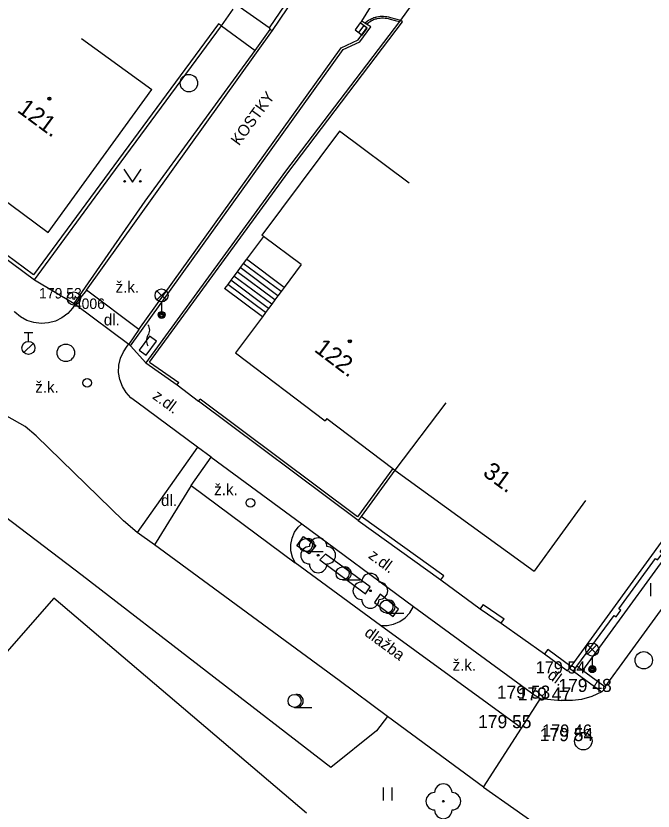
# Model space of a CAD drawing. Extents: x -538441 to -536770, y -1181008 to -1179809.
# Drawn here: x -537585.27 to -537548.66, y -1180631.14 to -1180585.46 of the extents above; entities that cross this region are included whole.
import ezdxf

# ---------------------------------------------------------------- set-up
doc = ezdxf.new("R2010")
doc.units = 0
for name, color, linetype in [('Vrstva 10', 7, 'Continuous'), ('Vrstva 11', 7, 'Continuous'), ('Vrstva 21', 7, 'Continuous'), ('Vrstva 22', 7, 'Continuous'), ('Vrstva 23', 7, 'Continuous'), ('Vrstva 24', 7, 'Continuous'), ('Vrstva 27', 7, 'Continuous'), ('Vrstva 28', 7, 'Continuous'), ('Vrstva 33', 7, 'Continuous'), ('Vrstva 36', 7, 'Continuous'), ('Vrstva 39', 7, 'Continuous'), ('Vrstva 4', 7, 'Continuous'), ('Vrstva 40', 7, 'Continuous'), ('Vrstva 47', 7, 'Continuous'), ('Vrstva 5', 7, 'Continuous'), ('Vrstva 7', 7, 'Continuous'), ('Vrstva 8', 7, 'Continuous')]:
    doc.layers.add(name, color=color, linetype=linetype)

msp = doc.modelspace()

# ---------------------------------------------------------------- linework, layer by layer
at = {"layer": 'Vrstva 10'}
for p, q in [((-537565.39, -1180585.76), (-537561.54, -1180579.49)), ((-537570.52, -1180586.29), (-537567.1, -1180581.19)), ((-537565.48, -1180585.86), (-537565.39, -1180585.76)), ((-537581.222, -1180601.219), (-537570.52, -1180586.29)), ((-537578.205, -1180603.471), (-537566.58, -1180587.29)), ((-537581.222, -1180601.219), (-537581.855, -1180602.02)), ((-537578.205, -1180603.471), (-537581.222, -1180601.219)), ((-537581.855, -1180602.02), (-537582.009, -1180602.238)), ((-537581.855, -1180602.02), (-537578.787, -1180604.314)), ((-537578.205, -1180603.471), (-537578.787, -1180604.314)), ((-537578.879, -1180604.43), (-537578.787, -1180604.314)), ((-537574.844, -1180610.221), (-537578.323, -1180607.637)), ((-537579.093, -1180614.456), (-537584.102, -1180609.571)), ((-537574.844, -1180610.221), (-537578.3, -1180615.128)), ((-537574.041, -1180610.808), (-537574.844, -1180610.221)), ((-537575.196, -1180612.441), (-537574.041, -1180610.808)), ((-537574.041, -1180610.808), (-537568.847, -1180614.632)), ((-537575.196, -1180612.441), (-537577.305, -1180615.844)), ((-537575.196, -1180612.441), (-537569.213, -1180616.879)), ((-537578.3, -1180615.128), (-537579.093, -1180614.456)), ((-537544.414, -1180614.353), (-537551.437, -1180623.991)), ((-537577.305, -1180615.844), (-537578.3, -1180615.128)), ((-537566.699, -1180623.637), (-537577.305, -1180615.844)), ((-537564.327, -1180620.468), (-537569.213, -1180616.879)), ((-537562.417, -1180619.388), (-537555.435, -1180624.491)), ((-537556.21, -1180626.37), (-537564.327, -1180620.468)), ((-537563.91, -1180625.71), (-537566.699, -1180623.637)), ((-537555.435, -1180624.491), (-537555.134, -1180624.676)), ((-537556.21, -1180626.37), (-537555.134, -1180624.676)), ((-537555.134, -1180624.676), (-537553.93, -1180624.78)), ((-537558.407, -1180629.756), (-537563.91, -1180625.71)), ((-537558.407, -1180629.756), (-537556.21, -1180626.37)), ((-537558.407, -1180629.756), (-537552.23, -1180634.08))]:
    msp.add_line(p, q, dxfattribs=at)
for points in [[(-537565.225, -1180585.865), (-537565.057, -1180585.747), (-537565, -1180585.71), (-537564.912, -1180585.658), (-537564.82, -1180585.61), (-537564.755, -1180585.58), (-537564.693, -1180585.556), (-537564.634, -1180585.537), (-537564.579, -1180585.521), (-537564.527, -1180585.508), (-537564.428, -1180585.49), (-537564.341, -1180585.48), (-537564.265, -1180585.475), (-537564.198, -1180585.475), (-537564.14, -1180585.476), (-537564.038, -1180585.484), (-537563.962, -1180585.493), (-537563.85, -1180585.514), (-537563.74, -1180585.541), (-537563.455, -1180585.62), (-537563.17, -1180585.7)], [(-537566.58, -1180587.29), (-537565.6, -1180586.83), (-537565.1, -1180586.15), (-537565.48, -1180585.86)], [(-537582.009, -1180602.238), (-537582.29, -1180602.549), (-537582.624, -1180602.8), (-537583.001, -1180602.984), (-537583.405, -1180603.093), (-537583.823, -1180603.123), (-537584.238, -1180603.073), (-537584.637, -1180602.946), (-537585.004, -1180602.745), (-537585.327, -1180602.478), (-537585.371, -1180602.432)], [(-537578.323, -1180607.637), (-537578.656, -1180607.393), (-537578.937, -1180607.089), (-537579.153, -1180606.736), (-537579.298, -1180606.349), (-537579.366, -1180605.941), (-537579.354, -1180605.528), (-537579.263, -1180605.125), (-537579.096, -1180604.747), (-537578.879, -1180604.43)], [(-537584.102, -1180609.571), (-537584.746, -1180609.048), (-537585.782, -1180608.449)], [(-537569.213, -1180616.879), (-537569.376, -1180616.548), (-537569.465, -1180616.189), (-537569.474, -1180615.82), (-537569.404, -1180615.457), (-537569.258, -1180615.118), (-537569.042, -1180614.818), (-537568.847, -1180614.632)], [(-537564.327, -1180620.468), (-537563.943, -1180620.474), (-537563.566, -1180620.401), (-537563.212, -1180620.252), (-537562.897, -1180620.033), (-537562.634, -1180619.753), (-537562.417, -1180619.388)], [(-537551.6, -1180624.29), (-537552.185, -1180624.557), (-537552.76, -1180624.72), (-537553.279, -1180624.789), (-537553.93, -1180624.78)]]:
    msp.add_lwpolyline(points, dxfattribs=at)
at = {"layer": 'Vrstva 11'}
for p, q in [((-537567.3, -1180581.08), (-537570.72, -1180586.14)), ((-537573.46, -1180586.03), (-537571.528, -1180587.436)), ((-537578.691, -1180604.418), (-537566.47, -1180587.38)), ((-537570.032, -1180601.294), (-537572.205, -1180599.676)), ((-537569.852, -1180601.053), (-537572.025, -1180599.435)), ((-537570.39, -1180601.775), (-537572.563, -1180600.157)), ((-537570.211, -1180601.534), (-537572.384, -1180599.916)), ((-537570.748, -1180602.256), (-537572.921, -1180600.638)), ((-537570.569, -1180602.016), (-537572.742, -1180600.398)), ((-537571.107, -1180602.738), (-537573.28, -1180601.12)), ((-537570.927, -1180602.497), (-537573.1, -1180600.879)), ((-537545.644, -1180613.334), (-537552.706, -1180623.054)), ((-537568.847, -1180614.632), (-537562.417, -1180619.388)), ((-537583.093, -1180618.912), (-537593.47, -1180630.74)), ((-537568.58, -1180631.25), (-537583.093, -1180618.912))]:
    msp.add_line(p, q, dxfattribs=at)
for points in [[(-537570.72, -1180586.14), (-537572.71, -1180584.74), (-537570.658, -1180581.969)], [(-537565.133, -1180585.923), (-537565.001, -1180585.83), (-537564.947, -1180585.795), (-537564.863, -1180585.745), (-537564.776, -1180585.7), (-537564.716, -1180585.672), (-537564.66, -1180585.65), (-537564.605, -1180585.633), (-537564.553, -1180585.618), (-537564.506, -1180585.606), (-537564.413, -1180585.589), (-537564.332, -1180585.58), (-537564.262, -1180585.575), (-537564.199, -1180585.575), (-537564.145, -1180585.576), (-537564.048, -1180585.584), (-537563.977, -1180585.592), (-537563.871, -1180585.612), (-537563.765, -1180585.638), (-537563.482, -1180585.716), (-537563.235, -1180585.785)], [(-537570.72, -1180586.14), (-537570.65, -1180586.23), (-537570.52, -1180586.29)], [(-537566.47, -1180587.38), (-537565.5, -1180586.94), (-537564.87, -1180586.09), (-537565.133, -1180585.923), (-537565.225, -1180585.865), (-537565.39, -1180585.76)], [(-537571.528, -1180587.436), (-537570.65, -1180586.23)], [(-537577.837, -1180596.095), (-537571.528, -1180587.436)], [(-537581.926, -1180601.978), (-537577.837, -1180596.095)], [(-537571.051, -1180598.126), (-537572.025, -1180599.435), (-537572.205, -1180599.676), (-537572.384, -1180599.916), (-537572.563, -1180600.157), (-537572.742, -1180600.398), (-537572.921, -1180600.638), (-537573.1, -1180600.879), (-537573.28, -1180601.12)], [(-537584.21, -1180600.62), (-537581.926, -1180601.978), (-537581.855, -1180602.02)], [(-537577.8, -1180605.38), (-537578.691, -1180604.418), (-537578.787, -1180604.314)]]:
    msp.add_lwpolyline(points, dxfattribs=at)
at = {"layer": 'Vrstva 21'}
for points in [[(-537563.91, -1180625.71), (-537564.55, -1180626.53), (-537567.18, -1180628.63), (-537581.47, -1180617.6), (-537593.01, -1180608.83)], [(-537568.74, -1180615.36), (-537568.03, -1180615.87), (-537568.42, -1180616.36), (-537569.12, -1180615.89), (-537568.74, -1180615.36)], [(-537567.48, -1180616.37), (-537567.8, -1180616.71), (-537565.19, -1180618.65), (-537564.91, -1180618.25), (-537567.48, -1180616.37)], [(-537564.66, -1180619.15), (-537563.59, -1180619.95), (-537563.29, -1180619.53), (-537564.33, -1180618.67), (-537564.66, -1180619.15)]]:
    msp.add_lwpolyline(points, dxfattribs=at)
for radius in [0.375, 0.05]:
    msp.add_circle((-537581.94, -1180601.69), radius, dxfattribs=at)
at = {"layer": 'Vrstva 22'}
for centre in [(-537567.9, -1180616.44), (-537564.9, -1180618.48), (-537560.71, -1180630.57)]:
    msp.add_circle(centre, 0.05, dxfattribs=at)
for centre, start, end in [((-537567.9, -1180615.94), 0, 180), ((-537568.4, -1180616.44), 90, 270), ((-537567.4, -1180616.44), 270, 90), ((-537567.9, -1180616.94), 180, 0), ((-537564.9, -1180617.98), 0, 180), ((-537565.4, -1180618.48), 90, 270), ((-537564.4, -1180618.48), 270, 90), ((-537564.9, -1180618.98), 180, 0), ((-537560.71, -1180630.07), 0, 180), ((-537561.21, -1180630.57), 90, 270), ((-537560.21, -1180630.57), 270, 90), ((-537560.71, -1180631.07), 180, 0)]:
    msp.add_arc(centre, 0.5, start, end, dxfattribs=at)
at = {"layer": 'Vrstva 24'}
msp.add_lwpolyline([(-537577.776, -1180604.951), (-537577.182, -1180604.146), (-537577.584, -1180603.849), (-537578.178, -1180604.654)], close=True, dxfattribs=at)
for centre, start, end in [((-537578.08, -1180603.5), 323.1301, 36.8699), ((-537577.28, -1180604.1), 143.1301, 216.8699)]:
    msp.add_arc(centre, 0.5, start, end, dxfattribs=at)
at = {"layer": 'Vrstva 27'}
msp.add_line((-537565.277, -1180586.009), (-537565.575, -1180586.411), dxfattribs=at)
msp.add_lwpolyline([(-537565.478, -1180585.86), (-537565.776, -1180586.262), (-537565.374, -1180586.56), (-537565.076, -1180586.158)], close=True, dxfattribs=at)
for centre in [(-537575.33, -1180589.32), (-537582.401, -1180604.81), (-537549.19, -1180622.47), (-537552.665, -1180627.117)]:
    msp.add_circle(centre, 0.5, dxfattribs=at)
at = {"layer": 'Vrstva 28'}
for p, q in [((-537584.798, -1180603.652), (-537584.298, -1180603.652)), ((-537584.548, -1180604.152), (-537584.548, -1180603.652)), ((-537584.806, -1180604.799), (-537584.276, -1180604.269))]:
    msp.add_line(p, q, dxfattribs=at)
for centre, radius in [((-537584.548, -1180604.527), 0.375), ((-537581.171, -1180606.53), 0.25), ((-537571.797, -1180613.431), 0.25)]:
    msp.add_circle(centre, radius, dxfattribs=at)
at = {"layer": 'Vrstva 33'}
for p, q in [((-537577.163, -1180601.775), (-537576.633, -1180601.245)), ((-537577.163, -1180601.245), (-537576.633, -1180601.775)), ((-537576.898, -1180601.885), (-537576.898, -1180602.635)), ((-537552.415, -1180622.12), (-537551.885, -1180621.59)), ((-537552.415, -1180621.59), (-537551.885, -1180622.12)), ((-537552.15, -1180622.23), (-537552.15, -1180622.98))]:
    msp.add_line(p, q, dxfattribs=at)
for centre, radius in [((-537576.898, -1180601.51), 0.375), ((-537576.898, -1180602.635), 0.2), ((-537576.898, -1180602.635), 0.145), ((-537576.898, -1180602.635), 0.0876), ((-537552.15, -1180621.855), 0.375), ((-537552.15, -1180622.98), 0.2), ((-537552.15, -1180622.98), 0.145), ((-537552.15, -1180622.98), 0.0876)]:
    msp.add_circle(centre, radius, dxfattribs=at)
at = {"layer": 'Vrstva 36'}
for p, q in [((-537568.606, -1180616.231), (-537567.606, -1180616.231)), ((-537566.497, -1180617.86), (-537565.497, -1180617.86)), ((-537548.782, -1180618.784), (-537548.782, -1180618.034)), ((-537563.978, -1180619.766), (-537562.978, -1180619.766)), ((-537569.256, -1180625.181), (-537568.256, -1180625.181)), ((-537564.147, -1180630.535), (-537564.147, -1180629.785)), ((-537563.647, -1180630.535), (-537563.647, -1180629.785))]:
    msp.add_line(p, q, dxfattribs=at)
msp.add_lwpolyline([(-537579.071, -1180594.26), (-537578.571, -1180595.01), (-537578.071, -1180594.26)], dxfattribs=at)
for centre, radius in [((-537579.021, -1180594.96), 0.05), ((-537578.122, -1180594.96), 0.05), ((-537568.606, -1180615.856), 0.375), ((-537566.497, -1180617.485), 0.375), ((-537563.978, -1180619.391), 0.375), ((-537569.256, -1180624.806), 0.375)]:
    msp.add_circle(centre, radius, dxfattribs=at)
for centre in [(-537568.481, -1180615.856), (-537566.372, -1180617.485), (-537563.853, -1180619.391), (-537569.131, -1180624.806)]:
    msp.add_arc(centre, 0.375, 260.4059, 99.5941, dxfattribs=at)
at = {"layer": 'Vrstva 39'}
for centre, radius in [((-537583.347, -1180590.215), 0.09), ((-537583.347, -1180590.215), 0.0398), ((-537566.079, -1180604.147), 0.09), ((-537566.079, -1180604.147), 0.0398)]:
    msp.add_circle(centre, radius, dxfattribs=at)
at = {"layer": 'Vrstva 5'}
for p, q in [((-537581.507, -1180586.754), (-537577.46, -1180589.69)), ((-537583.41, -1180597.89), (-537577.46, -1180589.69)), ((-537566.68, -1180592.07), (-537571.14, -1180598.06)), ((-537562.67, -1180595.056), (-537566.68, -1180592.07)), ((-537590.97, -1180592.33), (-537583.41, -1180597.89)), ((-537571.051, -1180598.126), (-537571.14, -1180598.06)), ((-537568.878, -1180599.744), (-537571.051, -1180598.126)), ((-537568.878, -1180599.744), (-537569.852, -1180601.053)), ((-537569.852, -1180601.053), (-537570.032, -1180601.294)), ((-537570.211, -1180601.534), (-537570.39, -1180601.775)), ((-537570.032, -1180601.294), (-537570.211, -1180601.534)), ((-537570.569, -1180602.016), (-537570.748, -1180602.256)), ((-537570.39, -1180601.775), (-537570.569, -1180602.016)), ((-537570.927, -1180602.497), (-537571.107, -1180602.738)), ((-537570.748, -1180602.256), (-537570.927, -1180602.497)), ((-537571.107, -1180602.738), (-537572.65, -1180604.81)), ((-537572.65, -1180604.81), (-537567.49, -1180608.71)), ((-537560.565, -1180607.675), (-537563.49, -1180611.545)), ((-537567.399, -1180608.59), (-537567.49, -1180608.71)), ((-537567.399, -1180608.59), (-537563.609, -1180611.455)), ((-537563.609, -1180611.455), (-537563.49, -1180611.545)), ((-537563.49, -1180611.545), (-537555.484, -1180617.35)), ((-537552.549, -1180613.302), (-537555.484, -1180617.35))]:
    msp.add_line(p, q, dxfattribs=at)
at = {"layer": 'Vrstva 7'}
for p, q in [((-537573.621, -1180585.911), (-537584.252, -1180600.34)), ((-537569.65, -1180594.47), (-537563.051, -1180585.791)), ((-537584.252, -1180600.34), (-537592.501, -1180594.219)), ((-537584.21, -1180600.62), (-537579.807, -1180594.644)), ((-537569.77, -1180594.38), (-537577.8, -1180605.38)), ((-537577.589, -1180605.345), (-537569.65, -1180594.47)), ((-537534.25, -1180596.49), (-537553.389, -1180622.832)), ((-537577.589, -1180605.345), (-537575.914, -1180606.517)), ((-537565.632, -1180614.239), (-537574.68, -1180607.47)), ((-537563.609, -1180611.455), (-537565.632, -1180614.239)), ((-537560.685, -1180617.616), (-537565.424, -1180614.207)), ((-537558.422, -1180619.272), (-537557.212, -1180620.092)), ((-537553.389, -1180622.832), (-537554.712, -1180621.858)), ((-537553.389, -1180622.832), (-537553.46, -1180622.93)), ((-537553.46, -1180622.93), (-537553.23, -1180623.09))]:
    msp.add_line(p, q, dxfattribs=at)
for points in [[(-537579.807, -1180594.644), (-537573.46, -1180586.03)], [(-537573.46, -1180586.03), (-537573.621, -1180585.911)], [(-537563.235, -1180585.785), (-537569.77, -1180594.38)], [(-537563.051, -1180585.791), (-537563.17, -1180585.7), (-537563.235, -1180585.785)], [(-537592.62, -1180594.38), (-537584.21, -1180600.62)], [(-537577.8, -1180605.38), (-537576, -1180606.64), (-537575.914, -1180606.517)], [(-537574.77, -1180607.59), (-537574.68, -1180607.47)], [(-537565.6, -1180614.45), (-537574.77, -1180607.59)], [(-537563.49, -1180611.545), (-537565.424, -1180614.207), (-537565.6, -1180614.45)], [(-537550.9, -1180619.89), (-537550.78, -1180619.98), (-537550.5, -1180619.6), (-537550.62, -1180619.51), (-537548.52, -1180616.62), (-537548.4, -1180616.71), (-537548.12, -1180616.33), (-537548.24, -1180616.24), (-537546.15, -1180613.37)], [(-537565.6, -1180614.45), (-537560.86, -1180617.86)], [(-537560.86, -1180617.86), (-537560.685, -1180617.616)], [(-537558.422, -1180619.272), (-537558.59, -1180619.52), (-537557.38, -1180620.34), (-537557.212, -1180620.092)], [(-537553.23, -1180623.09), (-537553.03, -1180622.815), (-537550.9, -1180619.89)], [(-537554.712, -1180621.858), (-537554.89, -1180622.1), (-537553.566, -1180623.075), (-537553.46, -1180622.93)], [(-537553.23, -1180623.09), (-537551.6, -1180624.29), (-537551.37, -1180624.04), (-537551.437, -1180623.991), (-537552.706, -1180623.054), (-537553.03, -1180622.815)]]:
    msp.add_lwpolyline(points, dxfattribs=at)
at = {"layer": 'Vrstva 8'}
for p, q in [((-537561.19, -1180582.96), (-537563.17, -1180585.7)), ((-537573.46, -1180586.03), (-537572.779, -1180585.071)), ((-537576, -1180606.64), (-537574.77, -1180607.59)), ((-537560.86, -1180617.86), (-537558.59, -1180619.52)), ((-537557.38, -1180620.34), (-537554.89, -1180622.1))]:
    msp.add_line(p, q, dxfattribs=at)

# ---------------------------------------------------------------- texts
at = {"layer": 'Vrstva 22'}
msp.add_text('179.53 ', height=0.6, dxfattribs=at).set_placement((-537583.94, -1180601.69))
at = {"layer": 'Vrstva 23'}
msp.add_text('4006', height=0.6, dxfattribs=at).set_placement((-537581.94, -1180602.29))
at = {"layer": 'Vrstva 4'}
for s, height, p in [('179 54 ', 0.7, (-537555.403, -1180623.23)), ('179 48 ', 0.75, (-537554.1, -1180624.29)), ('179 53 ', 0.75, (-537557.634, -1180624.676)), ('179 47 ', 0.75, (-537556.43, -1180624.78)), ('179 55 ', 0.75, (-537558.71, -1180626.37)), ('179 46 ', 0.7, (-537555.033, -1180626.86)), ('179 54 ', 0.75, (-537555.165, -1180627.117))]:
    msp.add_text(s, height=height, dxfattribs=at).set_placement(p)
at = {"layer": 'Vrstva 40'}
for s, rotation, p in [('KOSTKY', 53.6829, (-537572.451, -1180592.952)), ('z.dl.', 323.3972, (-537577.466, -1180607.401)), ('z.dl.', 323.5112, (-537565.062, -1180616.561)), ('dlažba', 323.7821, (-537565.29, -1180621.007)), ('dl.', 323.848, (-537554.77, -1180623.449))]:
    msp.add_text(s, height=0.65, rotation=rotation, dxfattribs=at).set_placement(p)
for s, p in [('ž.k.', (-537579.542, -1180601.356)), ('dl.', (-537580.219, -1180603.235)), ('ž.k.', (-537584.159, -1180607.107)), ('ž.k.', (-537573.876, -1180612.988)), ('dl.', (-537576.927, -1180613.611)), ('ž.k.', (-537560.176, -1180623.068))]:
    msp.add_text(s, height=0.65, dxfattribs=at).set_placement(p)
at = {"layer": 'Vrstva 47'}
for s, rotation, p in [('121.', 323.6674, (-537585.25, -1180590.936)), ('122.', 322.9175, (-537568.177, -1180604.696)), ('31.', 324.0548, (-537558.497, -1180611.816))]:
    msp.add_text(s, height=1, rotation=rotation, dxfattribs=at).set_placement(p)

doc.saveas('drawing.dxf')
